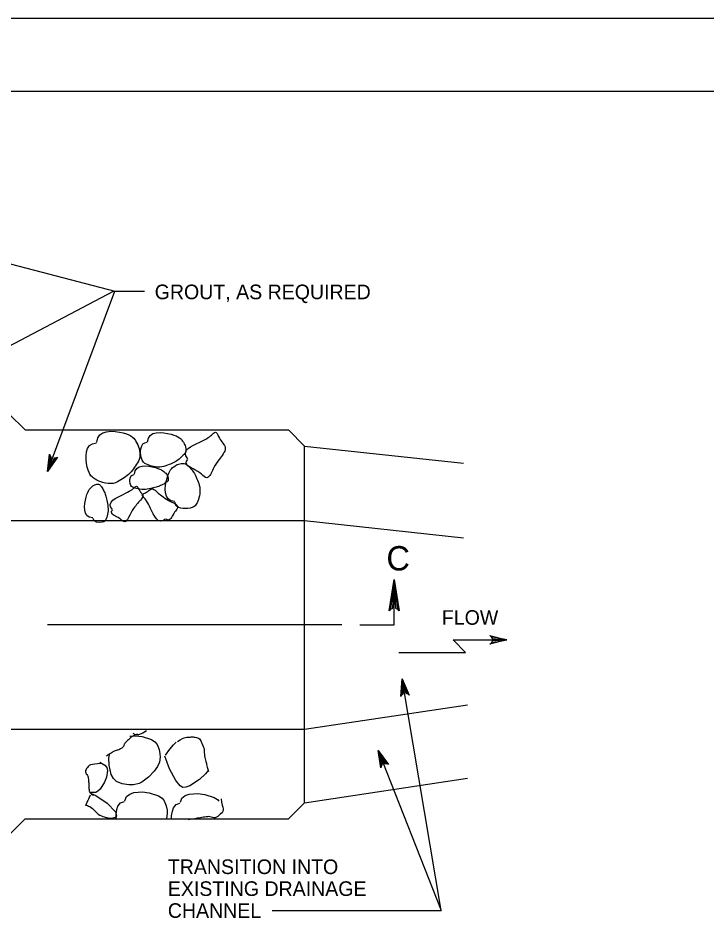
# Model space of a CAD drawing. Extents: x 636183 to 639890, y 299162 to 300538.
# Drawn here: x 638755.3 to 638896.5, y 300350.5 to 300538.4 of the extents above; entities that cross this region are included whole.
import ezdxf

# ---------------------------------------------------------------- set-up
doc = ezdxf.new("R2010")
doc.units = 0
for name, color, linetype in [('1', 7, 'Continuous'), ('Default', 7, 'Continuous'), ('PLT-BNDY', 7, 'Continuous')]:
    doc.layers.add(name, color=color, linetype=linetype)

msp = doc.modelspace()

# ---------------------------------------------------------------- linework, layer by layer
at = {"layer": '1'}
msp.add_lwpolyline([(638969.91, 299959.45), (638969.91, 300523.45), (638183.91, 300523.45), (638183.91, 299959.45), (638969.91, 299959.45), (638969.91, 299985.81), (638769.91, 299985.81), (638769.91, 300050.49), (638969.91, 300050.49), (638969.91, 300079.45), (638769.91, 300079.45), (638769.91, 299959.45), (638848.72, 299959.45), (638848.72, 299985.81), (638848.72, 299959.45), (638925.72, 299959.45), (638925.72, 299985.81), (638925.72, 299973.49), (638969.91, 299973.49)], dxfattribs=at)
at = {"layer": 'Default'}
for p, q in [((638775.05, 300482.43), (638781.18, 300482.43)), ((638756.67, 300453.96), (638753.35, 300457.28)), ((638756.67, 300453.96), (638810.69, 300453.96)), ((638814.02, 300450.63), (638810.69, 300453.96)), ((638814.02, 300450.63), (638846.63, 300447.12)), ((638814.02, 300377.42), (638814.02, 300450.63)), ((638733.59, 300435.35), (638814.02, 300435.35)), ((638814.02, 300435.35), (638846.63, 300431.83)), ((638832.41, 300413.92), (638832.41, 300423.25)), ((638821.68, 300413.92), (638761.29, 300413.92)), ((638825.37, 300413.92), (638832.41, 300413.92)), ((638814.02, 300392.5), (638847.43, 300397.55)), ((638733.59, 300392.5), (638814.02, 300392.5)), ((638778.17, 300391.1), (638779.29, 300391.19)), ((638778.84, 300391.66), (638778.83, 300391.67)), ((638779.34, 300391.36), (638778.84, 300391.66)), ((638779.29, 300391.19), (638780.7, 300391.03)), ((638779.96, 300391.38), (638779.34, 300391.36)), ((638780.8, 300391.7), (638779.96, 300391.38)), ((638780.7, 300391.03), (638782.6, 300390.41)), ((638781.58, 300392.22), (638780.8, 300391.7)), ((638782.6, 300390.41), (638783.31, 300389.95)), ((638783.31, 300389.95), (638783.78, 300389.4)), ((638783.78, 300389.4), (638784.18, 300388.37)), ((638786.39, 300388.44), (638787.13, 300389.34)), ((638787.13, 300389.34), (638787.64, 300389.85)), ((638773.87, 300386.59), (638774.02, 300387.51)), ((638784.18, 300388.37), (638784.34, 300387.47)), ((638784.34, 300387.47), (638784.36, 300386.76)), ((638786.32, 300384.42), (638785.36, 300387.02)), ((638785.47, 300387.19), (638786.39, 300388.44)), ((638771.98, 300385.74), (638773.03, 300385.17)), ((638773.03, 300385.17), (638773.42, 300384.67)), ((638773.9, 300385.12), (638773.87, 300386.59)), ((638774.34, 300383.25), (638773.9, 300385.12)), ((638784.22, 300385.74), (638783.83, 300384.84)), ((638784.36, 300386.76), (638784.22, 300385.74)), ((638773.55, 300384.04), (638773.35, 300382.69)), ((638773.42, 300384.67), (638773.55, 300384.04)), ((638774.77, 300382.4), (638774.34, 300383.25)), ((638783.17, 300383.93), (638781.99, 300382.69)), ((638783.83, 300384.84), (638783.17, 300383.93)), ((638787.6, 300381.97), (638786.32, 300384.42)), ((638793.71, 300383.39), (638792.44, 300382.23)), ((638794.2, 300384.05), (638793.71, 300383.39)), ((638772.95, 300381.62), (638772.09, 300380.25)), ((638773.35, 300382.69), (638772.95, 300381.62)), ((638775.41, 300381.77), (638774.77, 300382.4)), ((638776.57, 300381.3), (638775.41, 300381.77)), ((638777.94, 300381.08), (638776.57, 300381.3)), ((638780.06, 300381.36), (638778.88, 300381.09)), ((638780.65, 300381.66), (638780.06, 300381.36)), ((638781.99, 300382.69), (638780.65, 300381.66)), ((638788.5, 300380.88), (638787.6, 300381.97)), ((638792.44, 300382.23), (638790.46, 300380.92)), ((638814.02, 300377.42), (638847.43, 300382.47)), ((638771.15, 300379.54), (638770.15, 300379.5)), ((638771.62, 300379.78), (638771.15, 300379.54)), ((638772.09, 300380.25), (638771.62, 300379.78)), ((638778.88, 300381.09), (638777.94, 300381.08)), ((638778.14, 300379.22), (638778.97, 300379.5)), ((638778.97, 300379.5), (638780.74, 300379.64)), ((638780.74, 300379.64), (638782.15, 300379.48)), ((638782.15, 300379.48), (638784.05, 300378.86)), ((638789, 300380.59), (638788.5, 300380.88)), ((638789.62, 300380.6), (638789, 300380.59)), ((638790.46, 300380.92), (638789.62, 300380.6)), ((638770.21, 300379.31), (638771.16, 300378.93)), ((638771.16, 300378.93), (638773.47, 300377.35)), ((638776.25, 300377.41), (638777.03, 300377.68)), ((638777.15, 300377.85), (638777.46, 300378.71)), ((638777.46, 300378.71), (638778.14, 300379.22)), ((638784.05, 300378.86), (638784.76, 300378.4)), ((638784.76, 300378.4), (638785.23, 300377.85)), ((638785.23, 300377.85), (638785.63, 300376.82)), ((638788.54, 300377.52), (638788.85, 300378.38)), ((638788.85, 300378.38), (638789.53, 300378.89)), ((638789.53, 300378.89), (638790.36, 300379.17)), ((638790.36, 300379.17), (638792.13, 300379.31)), ((638792.13, 300379.31), (638793.55, 300379.15)), ((638793.55, 300379.15), (638795.44, 300378.53)), ((638795.44, 300378.53), (638796.15, 300378.07)), ((638796.15, 300378.07), (638796.44, 300377.73)), ((638773.47, 300377.35), (638775.24, 300375.57)), ((638775.32, 300375.05), (638775.48, 300376.06)), ((638775.48, 300376.06), (638775.72, 300376.7)), ((638775.72, 300376.7), (638776.25, 300377.41)), ((638785.63, 300376.82), (638785.79, 300375.92)), ((638785.79, 300375.92), (638785.81, 300375.22)), ((638786.71, 300374.71), (638786.88, 300375.72)), ((638786.88, 300375.72), (638787.11, 300376.37)), ((638787.11, 300376.37), (638787.65, 300377.07)), ((638787.65, 300377.07), (638788.43, 300377.35)), ((638810.69, 300374.1), (638814.02, 300377.42)), ((638753.35, 300370.77), (638756.67, 300374.1)), ((638756.67, 300374.1), (638810.69, 300374.1)), ((638775.24, 300375.57), (638775.45, 300374.77)), ((638775.45, 300374.77), (638775.24, 300374.1)), ((638775.34, 300374.1), (638775.32, 300375.05)), ((638785.67, 300374.19), (638785.63, 300374.1)), ((638785.81, 300375.22), (638785.67, 300374.19)), ((638786.73, 300374.1), (638786.71, 300374.71))]:
    msp.add_line(p, q, dxfattribs=at)
for points in [[(638740.21, 300491.57), (638775.05, 300482.43)], [(638703.59, 300444.96), (638774.83, 300482.43)], [(638761.29, 300445.4), (638775.05, 300482.43)], [(638763.02, 300448.21), (638763.32, 300448.38), (638761.29, 300445.4), (638763.02, 300448.21), (638762.6, 300448.15), (638761.29, 300445.4), (638762.11, 300448.33), (638761.82, 300448.63), (638761.29, 300445.4), (638761.68, 300448.98), (638761.82, 300448.63)], [(638831.65, 300417.15), (638832.09, 300417.38), (638832.41, 300423.25), (638831.65, 300417.15), (638831.38, 300416.84), (638832.41, 300423.25), (638832.7, 300417.38), (638833.14, 300417.17), (638832.41, 300423.25), (638833.43, 300416.84), (638833.14, 300417.17)], [(638852.3, 300411.5), (638852.03, 300411.73), (638855.54, 300410.88), (638852.3, 300411.5), (638852.5, 300411.13), (638855.54, 300410.88), (638852.51, 300410.61), (638852.33, 300410.23), (638855.54, 300410.88), (638852.05, 300409.98), (638852.33, 300410.23)], [(638833.35, 300408.29), (638847.06, 300408.29), (638844.48, 300410.88), (638855.54, 300410.88)], [(638807.38, 300355.34), (638842.03, 300355.34), (638834.01, 300402.84)], [(638833.91, 300399.55), (638833.74, 300399.25), (638834.01, 300402.84), (638833.91, 300399.55), (638834.25, 300399.81), (638834.01, 300402.84), (638834.77, 300399.9), (638835.17, 300399.78), (638834.01, 300402.84), (638835.46, 300399.54), (638835.17, 300399.78)], [(638829.13, 300388.18), (638842.03, 300355.34)], [(638829.74, 300384.95), (638829.63, 300384.61), (638829.13, 300388.18), (638829.74, 300384.95), (638830.01, 300385.27), (638829.13, 300388.18), (638830.5, 300385.47), (638830.91, 300385.44), (638829.13, 300388.18), (638831.25, 300385.27), (638830.91, 300385.44)]]:
    msp.add_lwpolyline(points, dxfattribs=at)
for points in [[(638771.4, 300451.46), (638771.44, 300454.15), (638778.33, 300453.54), (638779.49, 300451.46), (638780.14, 300450.28), (638780.37, 300448.17), (638779.54, 300446.91), (638778.73, 300445.66), (638777.6, 300444.53), (638776.36, 300443.72), (638774.91, 300442.78), (638772.45, 300443.06), (638771.12, 300443.83), (638769.22, 300444.92), (638768.8, 300451.23), (638771.29, 300451.29)], [(638781.81, 300451.51), (638781.85, 300453.93), (638787.93, 300453.18), (638789.08, 300451.51), (638789.52, 300450.88), (638789.78, 300449.43), (638789.13, 300448.77), (638788.32, 300447.95), (638787.31, 300447.3), (638786.26, 300446.86), (638784.84, 300446.27), (638782.88, 300446.34), (638781.55, 300446.93), (638780.29, 300447.49), (638780.21, 300451.38), (638781.71, 300451.41)], [(638790.08, 300448.05), (638788.44, 300449.8), (638793.49, 300451.63), (638795.22, 300453.2), (638795.87, 300453.79), (638796.55, 300452.15), (638797.19, 300451.3), (638797.99, 300450.23), (638797.31, 300448.99), (638796.51, 300447.92), (638795.41, 300446.46), (638794.24, 300443.59), (638793.13, 300444.64), (638792.07, 300445.63), (638789.05, 300446.84), (638790.08, 300447.91)], [(638779.1, 300444.88), (638779.17, 300447.06), (638784.55, 300446.25), (638785.65, 300444.88), (638785.93, 300444.54), (638786.15, 300443.56), (638785.7, 300443.24), (638784.91, 300442.69), (638784.01, 300442.33), (638783.12, 300442.09), (638781.77, 300441.74), (638780.16, 300441.71), (638778.87, 300442.14), (638778.06, 300442.41), (638778.12, 300444.81), (638779.01, 300444.82)], [(638787.36, 300439.26), (638784.94, 300439.3), (638785.69, 300445.38), (638787.36, 300446.53), (638787.99, 300446.96), (638789.44, 300447.23), (638790.1, 300446.58), (638790.92, 300445.77), (638791.57, 300444.76), (638792.01, 300443.71), (638792.6, 300442.29), (638792.53, 300440.33), (638791.94, 300439), (638791.38, 300437.74), (638787.49, 300437.66), (638787.46, 300439.15)], [(638770.54, 300435.89), (638768.36, 300435.95), (638769.18, 300441.33), (638770.54, 300442.44), (638770.89, 300442.71), (638771.87, 300442.94), (638772.18, 300442.48), (638772.73, 300441.7), (638773.09, 300440.8), (638773.33, 300439.9), (638773.68, 300438.55), (638773.72, 300436.95), (638773.29, 300435.66), (638773.02, 300434.84), (638770.61, 300434.9), (638770.61, 300435.8)], [(638774.6, 300437.61), (638773.15, 300439.2), (638777.67, 300440.92), (638779.24, 300442.24), (638779.63, 300442.57), (638780.06, 300441.6), (638780.43, 300441.11), (638781.06, 300440.27), (638780.07, 300439.32), (638779.41, 300438.47), (638778.42, 300437.2), (638777.38, 300434.68), (638776.38, 300435.5), (638775.75, 300436.03), (638773.97, 300436.86), (638774.58, 300437.5)], [(638785.5, 300435.66), (638783.92, 300434.21), (638782.2, 300438.72), (638780.87, 300440.29), (638780.54, 300440.68), (638781.51, 300441.12), (638782, 300441.48), (638782.85, 300442.11), (638783.79, 300441.13), (638784.64, 300440.47), (638785.91, 300439.48), (638788.43, 300438.44), (638787.61, 300437.44), (638787.09, 300436.81), (638786.25, 300435.01), (638785.61, 300435.64)], [(638779.72, 300391.48), (638778.78, 300391.22), (638778.01, 300390.52), (638777.29, 300389.8), (638776.96, 300389.47), (638776.91, 300388.93), (638776.54, 300388.68), (638775.92, 300388.26), (638775.13, 300388.14), (638774.49, 300387.75), (638774.11, 300387.51), (638773.73, 300387.28), (638773.37, 300387)], [(638787.93, 300389.99), (638788.77, 300390.62), (638789.67, 300390.88), (638790.54, 300390.92), (638791.3, 300390.95), (638792.39, 300390.77), (638792.78, 300389.99), (638793.43, 300388.68), (638793.39, 300387.37), (638793.71, 300386.07), (638793.9, 300385.32), (638794.08, 300384.57), (638794.27, 300383.83)], [(638772.25, 300385.51), (638771.2, 300385.3), (638769.88, 300385.39), (638769.26, 300384.39), (638768.86, 300383.73), (638769.56, 300383.03), (638769.64, 300382.34), (638769.73, 300381.53), (638769.69, 300380.72), (638769.82, 300379.91), (638769.89, 300379.51), (638770.71, 300378.77), (638770.76, 300379.16)], [(638770.01, 300378.98), (638769.7, 300378.29), (638769.39, 300377.61), (638769.08, 300376.92), (638769.05, 300376.87), (638769.21, 300376.94), (638769.26, 300376.92), (638770.53, 300376.42), (638771.63, 300374.9), (638773, 300374.5), (638773.68, 300374.29), (638774.53, 300374.23), (638775.24, 300374.5)], [(638796.89, 300378.23), (638796.85, 300377.17), (638797.69, 300376.01), (638796.7, 300375.06), (638795.69, 300374.09), (638794.59, 300374.67), (638793.53, 300374.5), (638792.41, 300374.31), (638791.29, 300374.12), (638790.17, 300373.94)]]:
    msp.add_open_spline(points, degree=3, dxfattribs=at)
at = {"layer": 'PLT-BNDY'}
msp.add_lwpolyline([(638143.91, 300538.45), (638984.91, 300538.45), (638984.91, 299944.45), (638143.91, 299944.45)], close=True, dxfattribs=at)

# ---------------------------------------------------------------- texts
at = {"layer": 'Default'}
for s, height, p in [('GROUT, AS REQUIRED', 2.998, (638783.26, 300480.79)), ('C', 5, (638830.8, 300425.11)), ('FLOW', 2.998, (638842.18, 300413.96)), ('TRANSITION INTO', 2.998, (638785.95, 300362.79)), ('EXISTING DRAINAGE', 2.998, (638785.95, 300358.3)), ('CHANNEL', 2.998, (638785.95, 300353.8))]:
    msp.add_text(s, height=height, dxfattribs=at).set_placement(p)

doc.saveas('drawing.dxf')
